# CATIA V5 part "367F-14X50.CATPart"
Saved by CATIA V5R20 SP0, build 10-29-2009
Part number: 367F-14X50
Definition: NONE
Nomenclature: 367F-14X50
Source: Unknown
Description: 367F-14X50
Bounding box of the stored display mesh (mm): x 0 to 50, y -14 to 14, z -14 to 14
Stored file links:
  C:\Users\Utente\Desktop\IO LAVORO\3D X SITO CF\X SITO\PLASTICA\3D files 367\367F-14X50.CATPart
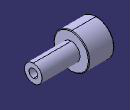
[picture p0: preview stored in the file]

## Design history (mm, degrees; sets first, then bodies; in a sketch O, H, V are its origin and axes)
Body1 "367F-14X50" (main body)
  Solid1: solid without history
